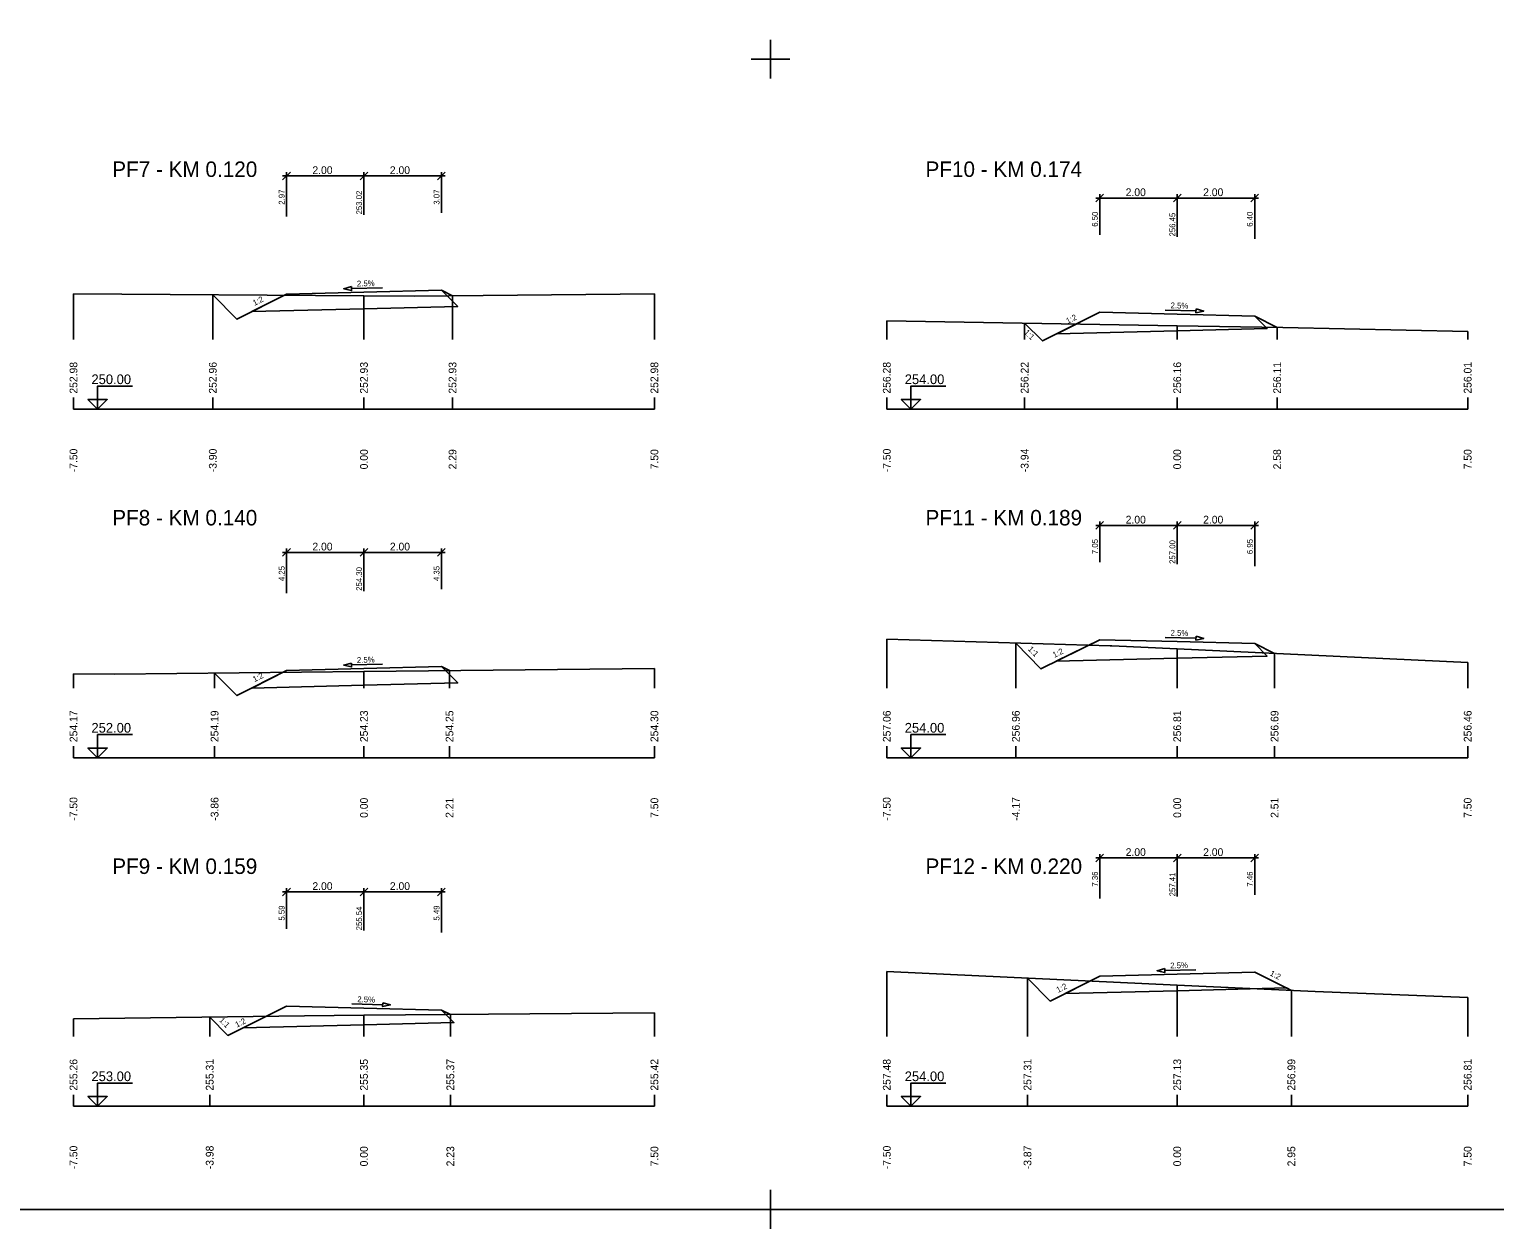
# Model space of a CAD drawing. Extents: x -5 to 1895, y -2 to 602.
# Drawn here: x 438.6 to 817, y -1.6 to 308.1 of the extents above; entities that cross this region are included whole.
import ezdxf

# ---------------------------------------------------------------- set-up
doc = ezdxf.new("R2010")
doc.units = 0
for name, color, linetype in [('KOTA', 7, 'Continuous'), ('KOTA_DELKY', 7, 'Continuous'), ('KOTA_DELKY_CONT', 7, 'Continuous'), ('NS_TELESO_VOZOVKY', 7, 'Continuous'), ('NS_V_PF', 7, 'Continuous'), ('REZY_PF_PUVODNI', 7, 'Continuous'), ('SESTAVY_REZU_PF', 7, 'Continuous'), ('SKLON', 7, 'Continuous'), ('SVK', 7, 'Continuous')]:
    doc.layers.add(name, color=color, linetype=linetype)

msp = doc.modelspace()

# ---------------------------------------------------------------- linework, layer by layer
for p, q in [((630, 305.39), (630, 295.39)), ((630, 305.39), (630, 295.39)), ((630, 305.39), (630, 295.39)), ((630, 305.39), (630, 295.39)), ((630, 305.39), (630, 295.39)), ((630, 305.39), (630, 295.39)), ((630, 305.39), (630, 295.39)), ((630, 305.39), (630, 295.39)), ((630, 305.39), (630, 295.39)), ((630, 305.39), (630, 295.39)), ((630, 305.39), (630, 295.39)), ((630, 305.39), (630, 295.39)), ((630, 305.39), (630, 295.39)), ((630, 305.39), (630, 295.39)), ((630, 305.39), (630, 295.39)), ((630, 305.39), (630, 295.39)), ((630, 305.39), (630, 295.39)), ((630, 305.39), (630, 295.39)), ((630, 305.39), (630, 295.39)), ((630, 305.39), (630, 295.39)), ((630, 305.39), (630, 295.39)), ((630, 305.39), (630, 295.39)), ((630, 305.39), (630, 295.39)), ((630, 305.39), (630, 295.39)), ((630, 305.39), (630, 295.39)), ((630, 305.39), (630, 295.39)), ((630, 305.39), (630, 295.39)), ((630, 305.39), (630, 295.39)), ((630, 305.39), (630, 295.39)), ((630, 305.39), (630, 295.39)), ((635, 300.39), (625, 300.39)), ((635, 300.39), (625, 300.39)), ((635, 300.39), (625, 300.39)), ((635, 300.39), (625, 300.39)), ((635, 300.39), (625, 300.39)), ((635, 300.39), (625, 300.39)), ((635, 300.39), (625, 300.39)), ((635, 300.39), (625, 300.39)), ((635, 300.39), (625, 300.39)), ((635, 300.39), (625, 300.39)), ((635, 300.39), (625, 300.39)), ((635, 300.39), (625, 300.39)), ((635, 300.39), (625, 300.39)), ((635, 300.39), (625, 300.39)), ((635, 300.39), (625, 300.39)), ((635, 300.39), (625, 300.39)), ((635, 300.39), (625, 300.39)), ((635, 300.39), (625, 300.39)), ((635, 300.39), (625, 300.39)), ((635, 300.39), (625, 300.39)), ((635, 300.39), (625, 300.39)), ((635, 300.39), (625, 300.39)), ((635, 300.39), (625, 300.39)), ((635, 300.39), (625, 300.39)), ((635, 300.39), (625, 300.39)), ((635, 300.39), (625, 300.39)), ((635, 300.39), (625, 300.39)), ((635, 300.39), (625, 300.39)), ((635, 300.39), (625, 300.39)), ((635, 300.39), (625, 300.39)), ((630, 8.39), (630, -1.61)), ((630, 8.39), (630, -1.61)), ((630, 8.39), (630, -1.61)), ((630, 8.39), (630, -1.61)), ((630, 8.39), (630, -1.61)), ((630, 8.39), (630, -1.61)), ((630, 8.39), (630, -1.61)), ((630, 8.39), (630, -1.61)), ((630, 8.39), (630, -1.61)), ((630, 8.39), (630, -1.61)), ((630, 8.39), (630, -1.61)), ((630, 8.39), (630, -1.61)), ((635, 3.39), (625, 3.39)), ((635, 3.39), (625, 3.39)), ((635, 3.39), (625, 3.39)), ((635, 3.39), (625, 3.39)), ((635, 3.39), (625, 3.39)), ((635, 3.39), (625, 3.39)), ((635, 3.39), (625, 3.39)), ((635, 3.39), (625, 3.39)), ((635, 3.39), (625, 3.39)), ((635, 3.39), (625, 3.39)), ((635, 3.39), (625, 3.39)), ((635, 3.39), (625, 3.39))]:
    msp.add_line(p, q)
msp.add_lwpolyline([(0, 597.39), (1890, 597.39), (1890, 3.39), (0, 3.39)], close=True)
at = {"layer": 'KOTA'}
for points in [[(456.22, 212.5), (453.72, 212.5), (456.22, 210), (456.22, 216), (465.22, 216)], [(666.22, 212.5), (663.72, 212.5), (666.22, 210), (666.22, 216), (675.22, 216)], [(456.22, 210), (458.72, 212.5), (456.22, 212.5)], [(666.22, 210), (668.72, 212.5), (666.22, 212.5)], [(456.22, 122.5), (453.72, 122.5), (456.22, 120), (456.22, 126), (465.22, 126)], [(666.22, 122.5), (663.72, 122.5), (666.22, 120), (666.22, 126), (675.22, 126)], [(456.22, 120), (458.72, 122.5), (456.22, 122.5)], [(666.22, 120), (668.72, 122.5), (666.22, 122.5)], [(456.22, 32.5), (453.72, 32.5), (456.22, 30), (456.22, 36), (465.22, 36)], [(666.22, 32.5), (663.72, 32.5), (666.22, 30), (666.22, 36), (675.22, 36)], [(456.22, 30), (458.72, 32.5), (456.22, 32.5)], [(666.22, 30), (668.72, 32.5), (666.22, 32.5)]]:
    msp.add_lwpolyline(points, dxfattribs=at)
at = {"layer": 'KOTA_DELKY'}
for points in [[(504, 269.25), (506, 271.25)], [(504, 270.25), (526, 270.25)], [(505, 259.75), (505, 271.25)], [(524, 269.25), (526, 271.25)], [(524, 269.25), (526, 271.25)], [(524, 270.25), (546, 270.25)], [(525, 260.25), (525, 271.25)], [(525, 260.25), (525, 271.25)], [(544, 269.25), (546, 271.25)], [(545, 260.75), (545, 271.25)], [(714, 263.55), (716, 265.55)], [(715, 255.05), (715, 265.55)], [(734, 263.55), (736, 265.55)], [(734, 263.55), (736, 265.55)], [(735, 254.55), (735, 265.55)], [(735, 254.55), (735, 265.55)], [(754, 263.55), (756, 265.55)], [(755, 254.05), (755, 265.55)], [(714, 264.55), (736, 264.55)], [(734, 264.55), (756, 264.55)], [(714, 179), (716, 181)], [(714, 180), (736, 180)], [(715, 170.5), (715, 181)], [(734, 179), (736, 181)], [(734, 179), (736, 181)], [(734, 180), (756, 180)], [(735, 170), (735, 181)], [(735, 170), (735, 181)], [(754, 179), (756, 181)], [(755, 169.5), (755, 181)], [(504, 172.04), (506, 174.04)], [(504, 173.04), (526, 173.04)], [(505, 162.54), (505, 174.04)], [(524, 172.04), (526, 174.04)], [(524, 172.04), (526, 174.04)], [(524, 173.04), (546, 173.04)], [(525, 163.04), (525, 174.04)], [(525, 163.04), (525, 174.04)], [(544, 172.04), (546, 174.04)], [(545, 163.54), (545, 174.04)], [(714, 93.14), (716, 95.14)], [(715, 83.64), (715, 95.14)], [(734, 93.14), (736, 95.14)], [(734, 93.14), (736, 95.14)], [(735, 84.14), (735, 95.14)], [(735, 84.14), (735, 95.14)], [(754, 93.14), (756, 95.14)], [(755, 84.64), (755, 95.14)], [(714, 94.14), (736, 94.14)], [(734, 94.14), (756, 94.14)], [(504, 84.36), (506, 86.36)], [(504, 85.36), (526, 85.36)], [(505, 75.86), (505, 86.36)], [(524, 84.36), (526, 86.36)], [(524, 84.36), (526, 86.36)], [(524, 85.36), (546, 85.36)], [(525, 75.36), (525, 86.36)], [(525, 75.36), (525, 86.36)], [(544, 84.36), (546, 86.36)], [(545, 74.86), (545, 86.36)]]:
    msp.add_lwpolyline(points, dxfattribs=at)
at = {"layer": 'NS_TELESO_VOZOVKY'}
for points in [[(525, 240.25), (545, 240.75), (545, 240.75), (549.2, 236.55), (525, 235.95), (496.05, 235.22), (505, 239.75), (505, 239.75), (525, 240.25)], [(735, 234.55), (755, 234.05), (755, 234.05), (758.22, 230.83), (735, 230.25), (703.9, 229.47), (715, 235.05), (715, 235.05), (735, 234.55)], [(735, 150), (755, 149.5), (755, 149.5), (758.22, 146.28), (735, 145.7), (703.77, 144.92), (715, 150.5), (715, 150.5), (735, 150)], [(525, 143.04), (545, 143.54), (545, 143.54), (549.2, 139.35), (525, 138.74), (496.05, 138.02), (505, 142.54), (505, 142.54), (525, 143.04)], [(735, 64.14), (755, 64.64), (755, 64.64), (764.47, 59.9), (763.19, 60.55), (735, 59.84), (706.05, 59.12), (715, 63.64), (715, 63.64), (735, 64.14)], [(525, 55.36), (545, 54.86), (545, 54.86), (548.22, 51.64), (525, 51.06), (493.83, 50.28), (505, 55.86), (505, 55.86), (525, 55.36)]]:
    msp.add_lwpolyline(points, dxfattribs=at)
at = {"layer": 'NS_V_PF'}
for points in [[(485.97, 239.56), (492.19, 233.27), (505, 239.75), (505, 239.75), (525, 240.25), (545, 240.75), (545, 240.75), (547.87, 239.31)], [(695.6, 232.22), (700.25, 227.64), (715, 235.05), (715, 235.05), (735, 234.55), (755, 234.05), (755, 234.05), (760.8, 231.15)], [(693.33, 149.64), (699.81, 142.95), (715, 150.5), (715, 150.5), (735, 150), (755, 149.5), (755, 149.5), (760.14, 146.93)], [(486.43, 141.89), (492.19, 136.07), (505, 142.54), (505, 142.54), (525, 143.04), (545, 143.54), (545, 143.54), (547.09, 142.5)], [(696.33, 63.08), (702.19, 57.16), (715, 63.64), (715, 63.64), (735, 64.14), (755, 64.64), (755, 64.64), (764.47, 59.9)], [(485.17, 53.05), (489.86, 48.29), (505, 55.86), (505, 55.86), (525, 55.36), (545, 54.86), (545, 54.86), (547.31, 53.71)]]:
    msp.add_lwpolyline(points, dxfattribs=at)
at = {"layer": 'REZY_PF_PUVODNI'}
for points in [[(450, 239.8), (525, 239.3), (538.01, 239.21), (600, 239.84)], [(660, 232.8), (735, 231.57), (762.28, 231.12), (810, 230.09)], [(660, 150.62), (717.65, 148.92), (718.15, 148.9), (735, 148.11), (810, 144.59)], [(450, 141.7), (460.6, 141.63), (525, 142.28), (600, 143.03)], [(660, 64.78), (735, 61.28), (770.58, 59.62), (810, 58.08)], [(450, 52.59), (509.65, 53.38), (525, 53.51), (600, 54.17)]]:
    msp.add_lwpolyline(points, dxfattribs=at)
at = {"layer": 'SESTAVY_REZU_PF'}
for points in [[(450, 210), (600, 210)], [(660, 210), (810, 210)], [(450, 120), (600, 120)], [(660, 120), (810, 120)], [(450, 30), (600, 30)], [(660, 30), (810, 30)]]:
    msp.add_lwpolyline(points, dxfattribs=at)
at = {"layer": 'SKLON'}
for points in [[(521.79, 241.67), (519.8, 241.12), (521.81, 240.67), (521.79, 241.67)], [(521.8, 241.17), (529.8, 241.37)], [(731.85, 235.63), (739.85, 235.43)], [(739.86, 235.93), (741.85, 235.38), (739.83, 234.93), (739.86, 235.93)], [(739.86, 151.38), (741.85, 150.83), (739.83, 150.38), (739.86, 151.38)], [(731.85, 151.08), (739.85, 150.88)], [(521.79, 144.47), (519.8, 143.92), (521.81, 143.47), (521.79, 144.47)], [(521.8, 143.97), (529.8, 144.17)], [(731.79, 65.56), (729.8, 65.01), (731.81, 64.56), (731.79, 65.56)], [(731.8, 65.06), (739.8, 65.26)], [(521.85, 56.44), (529.85, 56.24)], [(529.86, 56.74), (531.85, 56.19), (529.83, 55.74), (529.86, 56.74)]]:
    msp.add_lwpolyline(points, dxfattribs=at)
at = {"layer": 'SVK'}
for points in [[(450, 228), (450, 239.8)], [(485.97, 228), (485.97, 239.56)], [(525, 228), (525, 239.3)], [(547.87, 228), (547.87, 239.31)], [(600, 228), (600, 239.84)], [(660, 228), (660, 232.8)], [(695.6, 228), (695.6, 232.22)], [(735, 228), (735, 231.57)], [(760.8, 228), (760.8, 231.15)], [(810, 228), (810, 230.09)], [(450, 210), (450, 213)], [(485.97, 210), (485.97, 213)], [(525, 210), (525, 213)], [(547.87, 210), (547.87, 213)], [(600, 210), (600, 213)], [(660, 210), (660, 213)], [(695.6, 210), (695.6, 213)], [(735, 210), (735, 213)], [(760.8, 210), (760.8, 213)], [(810, 210), (810, 213)], [(660, 138), (660, 150.62)], [(693.33, 138), (693.33, 149.64)], [(735, 138), (735, 148.11)], [(760.14, 138), (760.14, 146.93)], [(810, 138), (810, 144.59)], [(450, 138), (450, 141.7)], [(486.43, 138), (486.43, 141.89)], [(525, 138), (525, 142.28)], [(547.09, 138), (547.09, 142.5)], [(600, 138), (600, 143.03)], [(450, 120), (450, 123)], [(486.43, 120), (486.43, 123)], [(525, 120), (525, 123)], [(547.09, 120), (547.09, 123)], [(600, 120), (600, 123)], [(660, 120), (660, 123)], [(693.33, 120), (693.33, 123)], [(735, 120), (735, 123)], [(760.14, 120), (760.14, 123)], [(810, 120), (810, 123)], [(660, 48), (660, 64.78)], [(696.33, 48), (696.33, 63.08)], [(735, 48), (735, 61.28)], [(764.47, 48), (764.47, 59.9)], [(810, 48), (810, 58.08)], [(485.17, 48), (485.17, 53.05)], [(525, 48), (525, 53.51)], [(547.31, 48), (547.31, 53.71)], [(600, 48), (600, 54.17)], [(450, 48), (450, 52.59)], [(450, 30), (450, 33)], [(485.17, 30), (485.17, 33)], [(525, 30), (525, 33)], [(547.31, 30), (547.31, 33)], [(600, 30), (600, 33)], [(660, 30), (660, 33)], [(696.33, 30), (696.33, 33)], [(735, 30), (735, 33)], [(764.47, 30), (764.47, 33)], [(810, 30), (810, 33)]]:
    msp.add_lwpolyline(points, dxfattribs=at)

# ---------------------------------------------------------------- texts
at = {"layer": 'KOTA'}
for s, p in [('250.00', (454.64, 216.5)), ('254.00', (664.64, 216.5)), ('252.00', (454.64, 126.5)), ('254.00', (664.64, 126.5)), ('253.00', (454.64, 36.5)), ('254.00', (664.64, 36.5))]:
    msp.add_text(s, height=2.5, dxfattribs=at).set_placement(p)
at = {"layer": 'KOTA_DELKY'}
for p in [(511.69, 270.75), (531.69, 270.75), (721.69, 265.05), (741.69, 265.05), (721.69, 180.5), (741.69, 180.5), (511.69, 173.54), (531.69, 173.54), (721.69, 94.64), (741.69, 94.64), (511.69, 85.86), (531.69, 85.86)]:
    msp.add_text('2.00', height=2, dxfattribs=at).set_placement(p)
at = {"layer": 'KOTA_DELKY_CONT'}
for s, p in [('2.97', (504.5, 262.84)), ('253.02', (524.5, 260.32)), ('3.07', (544.5, 262.84)), ('6.50', (714.5, 257.14)), ('256.45', (734.5, 254.62)), ('6.40', (754.5, 257.14)), ('7.05', (714.5, 172.59)), ('257.00', (734.5, 170.08)), ('6.95', (754.5, 172.59)), ('4.25', (504.5, 165.63)), ('254.30', (524.5, 163.12)), ('4.35', (544.5, 165.63)), ('7.36', (714.5, 86.73)), ('257.41', (734.5, 84.22)), ('7.46', (754.5, 86.73)), ('5.59', (504.5, 77.95)), ('255.54', (524.5, 75.44)), ('5.49', (544.5, 77.95))]:
    msp.add_text(s, height=1.5, rotation=90, dxfattribs=at).set_placement(p)
at = {"layer": 'SESTAVY_REZU_PF'}
for s, p in [('PF7 - KM 0.120', (460, 270)), ('PF10 - KM 0.174', (670, 270)), ('PF8 - KM 0.140', (460, 180)), ('PF11 - KM 0.189', (670, 180)), ('PF9 - KM 0.159', (460, 90)), ('PF12 - KM 0.220', (670, 90))]:
    msp.add_text(s, height=4, dxfattribs=at).set_placement(p)
at = {"layer": 'SKLON'}
for s, rotation, p in [('2.5%', 1.4321, (523.2, 241.7)), ('1:2', 26.8233, (496.74, 236.69)), ('2.5%', 358.5679, (733.27, 236.09)), ('1:2', 26.6688, (706.74, 232.02)), ('1:1', 315.4346, (695.32, 229.73)), ('2.5%', 358.5679, (733.27, 151.54)), ('1:1', 314.1179, (696.35, 147.95)), ('1:2', 26.4309, (703.28, 145.79)), ('2.5%', 1.4321, (523.2, 144.5)), ('1:2', 26.8233, (496.74, 139.49)), ('2.5%', 1.4321, (733.2, 65.6)), ('1:2', 333.4349, (758.77, 63.87)), ('1:2', 26.8233, (704.24, 59.26)), ('2.5%', 358.5679, (523.27, 56.9)), ('1:1', 314.5713, (487.52, 52.1)), ('1:2', 26.5484, (492.19, 50.28))]:
    msp.add_text(s, height=1.5, rotation=rotation, dxfattribs=at).set_placement(p)
at = {"layer": 'SVK'}
for s, p in [(' 252.98', (451, 213.3)), (' 252.96', (486.97, 213.3)), (' 252.93', (526, 213.3)), (' 252.93', (548.87, 213.3)), (' 252.98', (601, 213.3)), (' 256.28', (661, 213.3)), (' 256.22', (696.6, 213.3)), (' 256.16', (736, 213.3)), (' 256.11', (761.8, 213.3)), (' 256.01', (811, 213.3)), (' -7.50', (451, 193)), (' -3.90', (486.97, 193)), ('  0.00', (526, 193)), ('  2.29', (548.87, 193)), ('  7.50', (601, 193)), (' -7.50', (661, 193)), (' -3.94', (696.6, 193)), ('  0.00', (736, 193)), ('  2.58', (761.8, 193)), ('  7.50', (811, 193)), (' 254.17', (451, 123.3)), (' 254.19', (487.43, 123.3)), (' 254.23', (526, 123.3)), (' 254.25', (548.09, 123.3)), (' 254.30', (601, 123.3)), (' 257.06', (661, 123.3)), (' 256.96', (694.33, 123.3)), (' 256.81', (736, 123.3)), (' 256.69', (761.14, 123.3)), (' 256.46', (811, 123.3)), (' -7.50', (451, 103)), (' -7.50', (661, 103)), (' -3.86', (487.43, 103)), ('  0.00', (526, 103)), ('  2.21', (548.09, 103)), ('  7.50', (601, 103)), (' -4.17', (694.33, 103)), ('  0.00', (736, 103)), ('  2.51', (761.14, 103)), ('  7.50', (811, 103)), (' 255.26', (451, 33.3)), (' 255.31', (486.17, 33.3)), (' 255.35', (526, 33.3)), (' 255.37', (548.31, 33.3)), (' 255.42', (601, 33.3)), (' 257.48', (661, 33.3)), (' 257.31', (697.33, 33.3)), (' 257.13', (736, 33.3)), (' 256.99', (765.47, 33.3)), (' 256.81', (811, 33.3)), (' -7.50', (451, 13)), (' -3.98', (486.17, 13)), ('  0.00', (526, 13)), ('  2.23', (548.31, 13)), ('  7.50', (601, 13)), (' -7.50', (661, 13)), (' -3.87', (697.33, 13)), ('  0.00', (736, 13)), ('  2.95', (765.47, 13)), ('  7.50', (811, 13))]:
    msp.add_text(s, height=2, rotation=90, dxfattribs=at).set_placement(p)

doc.saveas('drawing.dxf')
